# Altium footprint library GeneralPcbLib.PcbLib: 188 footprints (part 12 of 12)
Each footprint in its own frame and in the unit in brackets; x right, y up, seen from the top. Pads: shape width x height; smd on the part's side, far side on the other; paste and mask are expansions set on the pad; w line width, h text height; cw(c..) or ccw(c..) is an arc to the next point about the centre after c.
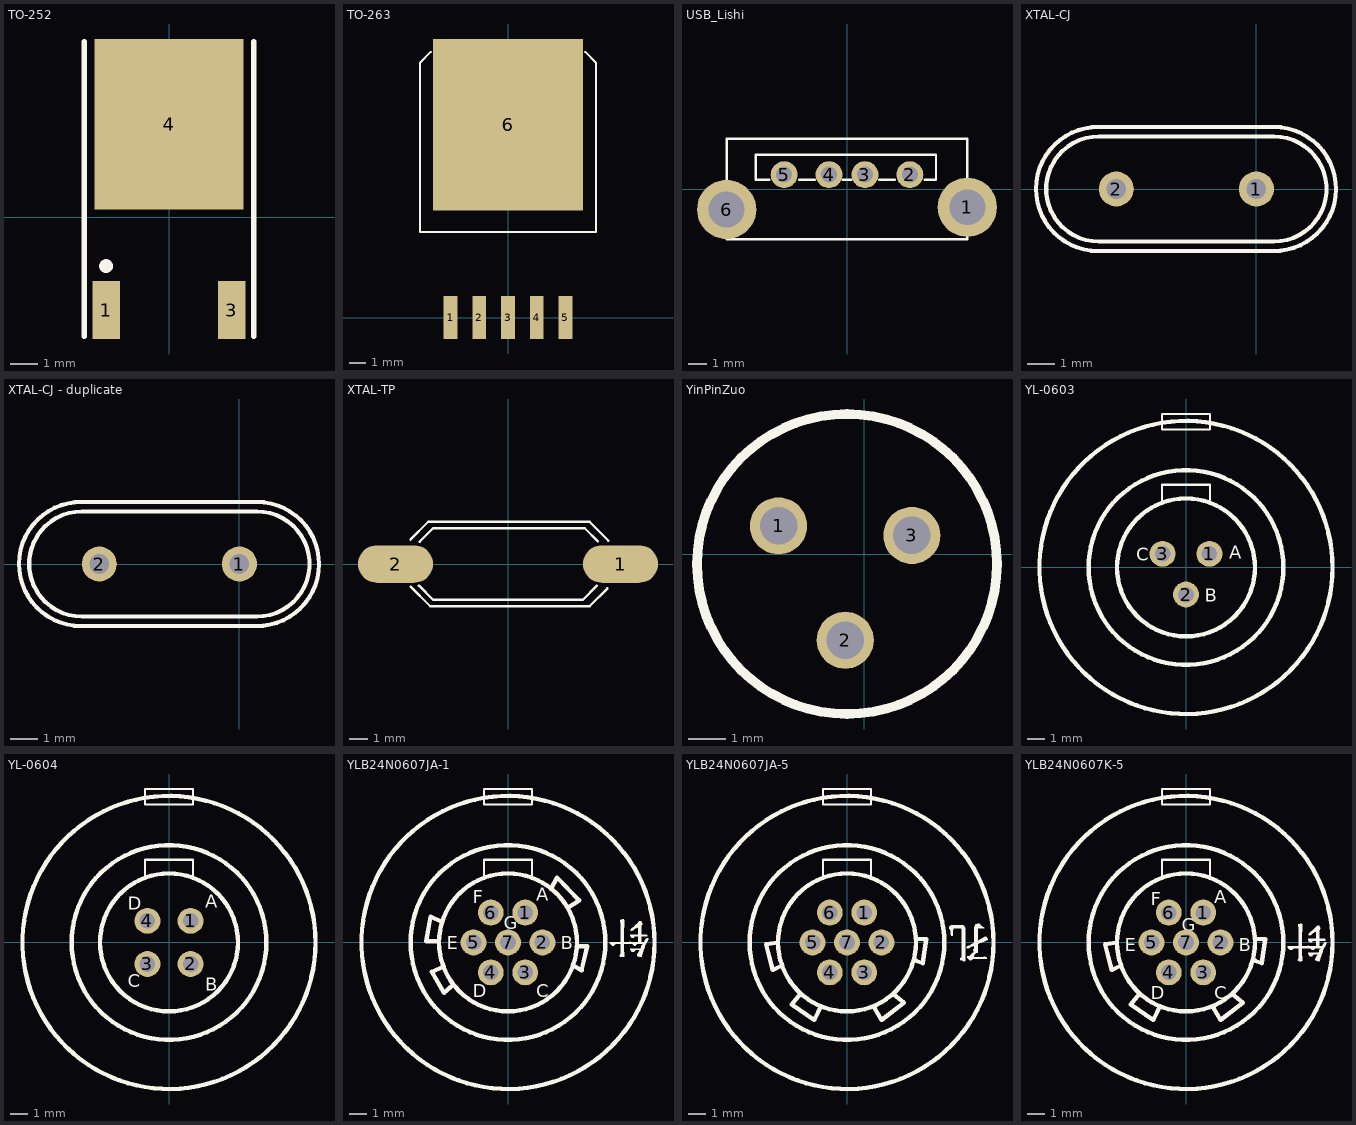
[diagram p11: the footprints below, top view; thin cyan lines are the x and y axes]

## TO-252 [mm] "D-PAK/TO-252-AA; 3 Leads (1 Cropped); Body 10.1 (inc. leads) x 6.6 mm (LxW max)"
height 2.4
pads (3):
  rect 1x2.1 smd: 1(-2.285,-3.375) 3(2.285,-3.375)
  rect 5.4x6.2 smd: 4(0,3.375)
Top Overlay:
  circle w0.25: c-2.285,-1.775 r0.125
  lines w0.2: -3.085,-4.325 -3.085,6.375 ; 3.085,-4.325 3.085,6.375
3D body: height 2.39, standoff -0.02, extent -3.27,-3.96 3.27,5.978

## TO-263 [mil] "BAORUI"
pads (6):
  rect 32x100 smd: 1(-134,0) 2(-67,0) 3(0,0) 4(67,0) 5(134,0)
  rect 350x400 smd: 6(0,450)
Top Overlay:
  lines w5: -180,620 -205,595 -205,200 205,200 205,595 180,620

## USB_Lishi [mm]
pads (6):
  round 3.3 hole 2: 1(6.7,-1.016) 6(-6.7,-1.143)
  round 1.5 hole 0.9: 2(3.5,0.8) 3(1,0.8) 4(-1,0.8) 5(-3.5,0.8)
Top Overlay:
  lines w0.127: -4.318,0.508 -5.08,0.508 -5.08,1.905 4.953,1.905 4.953,0.508 4.318,0.508 ; -2.667,0.508 -1.778,0.508 ; -1.254,0.381 -1.127,0.254 ; -0.254,0.508 0.254,0.508 ; 1,0.254 1.127,0.381 ; 1.778,0.508 2.667,0.508 ; -6.7,-2.8 6.7,-2.8 6.7,2.8 -6.7,2.8 -6.7,-2.8

## XTAL-CJ [mil]
pads (2):
  round 50 hole 28: 1(0,0) 2(-200,0)
Top Overlay:
  lines w6: -226,-88.58 cw(c-226,0) -225.09,88.58 25,88.58 cw(c25,0) 24.07,-88.58 -226,-88.58 ; -225,-75 cw(c-225,0) -225,75 25,75 cw(c25,0) 25,-75 -225,-75
3D body: height 137.8, standoff 0, extent -300.34,-75.34 100.34,75.34

## XTAL-CJ - duplicate [mil]
pads (2):
  round 50 hole 28: 1(0,0) 2(-200,0)
Top Overlay:
  lines w6: -226,-88.58 cw(c-226,0) -225.09,88.58 25,88.58 cw(c25,0) 24.07,-88.58 -226,-88.58 ; -225,-75 cw(c-225,0) -225,75 25,75 cw(c25,0) 25,-75 -225,-75
3D body: height 137.8, standoff 0, extent -300.34,-75.34 100.34,75.34

## XTAL-TP [mm] "贴片晶振"
pads (2):
  oval 4x2 smd: 1(6,0) 2(-6,0)
Top Overlay:
  lines w0.127: -5.2,-1.2 -4.15,-2.25 -3.2,-2.25 3.151,-2.25 4.35,-2.25 5.3,-1.3 ; -5.2,1.3 -4.25,2.25 -3.177,2.25 3.175,2.25 4.35,2.25 5.35,1.25 ; -4.75,-1.15 -3.995,-1.905 -3.175,-1.905 3.175,-1.905 3.995,-1.905 4.747,-1.153 ; -4.715,1.184 -3.995,1.905 -3.175,1.905 3.175,1.905 4.095,1.905 4.8,1.2

## YinPinZuo [mil] "平衡音频座"
pads (3):
  round 60 hole 39.37: 1(-90,30) 2(-20,-90) 3(50,20)
Top Overlay:
  circle w10: c-18.11,-10 r157.48

## YL-0603 [mm]
pads (3):
  round 1.5 hole 0.9: 1(1.36,0.79) 2(0,-1.57) 3(-1.36,0.79)
Top Overlay:
  circle w0.254: c0,0 r5.65
  circle w0.254: c0,0 r4
  circle w0.254: c0,0 r8.5
  lines w0.127: -1.4,3.8 -1.4,4.8 1.4,4.8 1.4,3.7 ; -1.4,8 1.4,8 1.4,8.9 -1.4,8.9 -1.4,8
  text "A" at 2.5,0.5 h0.76
  text "B" at 1.1,-2 h0.76
  text "C" at -2.9,0.4 h0.76

## YL-0604 [mm]
pads (4):
  round 1.5 hole 0.9: 1(1.25,1.25) 2(1.25,-1.25) 3(-1.25,-1.25) 4(-1.25,1.25)
Top Overlay:
  circle w0.254: c0,0 r8.5
  circle w0.254: c0,0 r4
  circle w0.254: c0,0 r5.65
  lines w0.127: -1.4,3.8 -1.4,4.8 1.4,4.8 1.4,3.7 ; -1.4,8 -1.4,8.9 1.4,8.9 1.4,8 -1.4,8
  text "D" at -2.4,1.9 h0.76
  text "C" at -2.4,-2.6 h0.76
  text "B" at 2.1,-2.8 h0.76
  text "A" at 2.1,2 h0.76

## YLB24N0607JA-1 [mm]
pads (7):
  round 1.5 hole 0.9: 1(1,1.735) 2(2,0) 3(1,-1.735) 4(-1,-1.735) 5(-2,0) 6(-1,1.735) 7(0,0)
Top Overlay:
  drawing of 219 lines, arcs and shapes, not listed
  text "A" at 1.651,2.413 h0.76
  text "B" at 3.048,-0.381 h0.76
  text "C" at 1.651,-3.175 h0.76
  text "D" at -2.032,-3.175 h0.76
  text "E" at -3.556,-0.381 h0.76
  text "F" at -2.032,2.286 h0.76
  text "G" at -0.254,0.762 h0.76

## YLB24N0607JA-5 [mm]
pads (7):
  round 1.5 hole 0.9: 1(1,1.735) 2(2,0) 3(1,-1.735) 4(-1,-1.735) 5(-2,0) 6(-1,1.735) 7(0,0)
Top Overlay:
  drawing of 221 lines, arcs and shapes, not listed

## YLB24N0607K-5 [mm]
pads (7):
  round 1.5 hole 0.9: 1(1,1.735) 2(2,0) 3(1,-1.735) 4(-1,-1.735) 5(-2,0) 6(-1,1.735) 7(0,0)
Top Overlay:
  drawing of 219 lines, arcs and shapes, not listed
  text "G" at -0.254,0.635 h0.76
  text "F" at -2.032,2.159 h0.76
  text "E" at -3.556,-0.508 h0.76
  text "D" at -2.032,-3.302 h0.76
  text "C" at 1.651,-3.302 h0.76
  text "B" at 3.048,-0.508 h0.76
  text "A" at 1.651,2.286 h0.76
